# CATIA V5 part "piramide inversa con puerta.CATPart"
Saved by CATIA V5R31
Part number: piramide inversa con puerta
Bounding box of the stored display mesh (mm): x -150 to 150, y 0 to 3.3, z 0 to 175
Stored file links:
  C:\Users\189361\Desktop\piramide inversa con puerta.CATPart
  C:\Users\189361\Desktop\pieamide inversa.CATPart
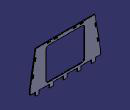
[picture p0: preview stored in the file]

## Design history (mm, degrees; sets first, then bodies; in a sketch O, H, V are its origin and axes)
Body1 (main body)
  Sketch1 on zx-plane, origin (0, 0, 0), H (-1, 0, 0), V (0, 0, 1)
    line L1 (-127.65, 15) -> (-150, 15)
    construction line L2 through (0, 0) direction (0, 1)
    line L3 (-150, 15) -> (-150, 35)
    point P1 (-127.65, 0)
    line L4 (-127.65, 15) -> (-127.65, 0)
    line L5 (-127.65, 0) -> (-112.35, 0)
    point P2 (-112.35, 15)
    line L6 (-112.35, 0) -> (-112.35, 15)
    line L7 (-112.35, 15) -> (-67.65, 15)
    point P3 (-67.65, 0)
    line L8 (-67.65, 15) -> (-67.65, 0)
    line L9 (-67.65, 0) -> (-52.35, 0)
    point P4 (-52.35, 15)
    line L10 (-52.35, 0) -> (-52.35, 15)
    point P5 (0, 20)
    construction line L11 (-120, 69.0879) -> (-120, 15.3646)
    construction line L12 (-60, 77.7749) -> (-60, 37.1309)
    point P6 (0, 20)
    line L13 (-52.35, 15) -> (-7.65, 15)
    point P7 (-7.65, 0)
    line L14 (-7.65, 15) -> (-7.65, 0)
    line L15 (-7.65, 0) -> (0, 0)
    point P8 (0, 20)
    point P9 (0, 20)
    point P10 (0, 0)
    point P11 (-127.65, 15)
    point P12 (-150, 15)
    point P13 (-150, 35)
    point P14 (-112.35, 0)
    point P15 (-67.65, 15)
    point P16 (-52.35, 0)
    point P17 (0, 20)
    point P18 (-120, 15.3646)
    point P19 (-120, 69.0879)
    point P20 (-60, 37.1309)
    point P21 (-60, 77.7749)
    point P22 (0, 20)
    point P23 (-7.65, 15)
    point P24 (0, 20)
    construction line L16 (0, 0) -> (0, 175)
    point P25 (0, 175)
    axis line L17 (0, 175) -> (-53, 175)
    point P26 (-53, 175)
    line L18 (0, 175) -> (-127, 175)
    point P27 (-127, 175)
    line L19 (-127, 175) -> (-150, 35)
    point P28 (0, 0)
    point P29 (127.65, 0)
    point P30 (112.35, 15)
    point P31 (67.65, 0)
    point P32 (52.35, 15)
    point P33 (0, 20)
    point P34 (120, 15.3646)
    point P35 (120, 69.0879)
    construction line L20 (120, 69.0879) -> (120, 15.3646)
    point P36 (60, 37.1309)
    point P37 (60, 77.7749)
    construction line L21 (60, 77.7749) -> (60, 37.1309)
    point P38 (0, 20)
    point P39 (7.65, 0)
    point P40 (0, 20)
    point P41 (0, 20)
    point P42 (0, 0)
    point P43 (127.65, 15)
    point P44 (150, 15)
    point P45 (150, 35)
    point P46 (112.35, 0)
    point P47 (67.65, 15)
    point P48 (52.35, 0)
    point P49 (0, 20)
    point P50 (0, 20)
    point P51 (7.65, 15)
    point P52 (0, 20)
    point P53 (0, 175)
    point P54 (53, 175)
    construction line L22 (0, 175) -> (53, 175)
    point P55 (127, 175)
    line L23 (127.65, 15) -> (150, 15)
    line L24 (150, 15) -> (150, 35)
    line L25 (127.65, 15) -> (127.65, 0)
    line L26 (127.65, 0) -> (112.35, 0)
    line L27 (112.35, 0) -> (112.35, 15)
    line L28 (112.35, 15) -> (67.65, 15)
    line L29 (67.65, 15) -> (67.65, 0)
    line L30 (67.65, 0) -> (52.35, 0)
    line L31 (52.35, 0) -> (52.35, 15)
    line L32 (52.35, 15) -> (7.65, 15)
    line L33 (7.65, 15) -> (7.65, 0)
    line L34 (7.65, 0) -> (0, 0)
    line L35 (0, 175) -> (127, 175)
    line L36 (127, 175) -> (150, 35)
    distance L11 L3 = 30
    distance L6 L11 = 7.65
    distance L12 L11 = 60
    distance L10 L12 = 7.65
    distance L2 L14 = 7.65
    length L14 = 15
    length L13 = 44.7
    length L3 = 20
    length L9 = 15.3
    length L16 = 175
    length L17 = 53
    length L18 = 127
    vertical: L3 L2, L4 L2, L6 L2, L8 L2, L10 L2, L11 L2, L12 L2, L16 V
    coincidence: P2 L1, P4 L1, P5 L2, O L2, L5 H, L13 L7, L15 H, P10 L2, P10 P42, P25 P53
    equal size: L4 L6, L6 L8, L8 L10, L9 L5, L10 L14, L14 L4
    symmetry: P5 P6 L2, P5 P8 L2, P6 P9 L2, P5 P17 L2, P6 P22 L2, P8 P24 L2, O P28 L16, P1 P29 L16, P2 P30 L16, P3 P31 L16, P4 P32 L16, P5 P33 L16, P18 P34 L16, P19 P35 L16, L11 L20 L16, P20 P36 L16, P21 P37 L16, L12 L21 L16, P6 P38 L16, P7 P39 L16, P8 P40 L16, P9 P41 L16, P10 P42 L16, P11 P43 L16, P12 P44 L16, P13 P45 L16, P14 P46 L16, P15 P47 L16, P16 P48 L16, P17 P49 L16, P22 P50 L16, P23 P51 L16, P24 P52 L16, P25 P53 L16, P26 P54 L16, L17 L22 L16, P27 P55 L16, L1 L23 L16, L3 L24 L16, L4 L25 L16, L5 L26 L16, L6 L27 L16, L7 L28 L16, L8 L29 L16, L9 L30 L16, L10 L31 L16, L13 L32 L16, L14 L33 L16, L15 L34 L16, L18 L35 L16, L19 L36 L16
    perpendicularity: L6 L7
    horizontal: L17 H, L18 H
  Pad1: profile Sketch1, direction (0, 1, 0), length 3.3
  Sketch2 on end face of Pad1, origin (0, 3.3, 0), H (-1, 0, 0), V (0, 0, 1)
    line L1 (-47.5, 172) -> (-32.5, 172)
    line L2 (-32.5, 168.7) -> (-47.5, 168.7)
    line L3 (-32.5, 172) -> (-32.5, 168.7)
    line L4 (-47.5, 168.7) -> (-47.5, 172)
    construction line L5 (-40, 200.409) -> (-40, 181.2846)
    line L6 (-141.3626, 69.0701) -> (-138.1062, 68.5351)
    line L7 (-138.1062, 68.5351) -> (-135.6745, 83.3367)
    line L8 (-135.6745, 83.3367) -> (-138.9309, 83.8717)
    line L9 (-138.9309, 83.8717) -> (-141.3626, 69.0701)
    construction line L10 (-146.6312, 37) -> (-125.5566, 165.2804)
    construction line L11 (-143.6709, 36.5137) -> (-146.6312, 37)
    construction line L12 (-122.5963, 164.7941) -> (-143.6709, 36.5137)
    construction line L13 (-125.5566, 165.2804) -> (-122.5963, 164.7941)
    point P1 (-146.6312, 37)
    construction line L14 (-117.5, 169) -> (-117.5, 172)
    construction line L15 (-162.6915, 80.1747) -> (-181.1718, 83.2107)
    construction line L16 (-159.9601, 110.1281) -> (-179.3888, 113.32)
    point P2 (-129.2041, 143.078)
    point P3 (-141.3626, 69.0701)
    point P4 (-131.6358, 128.2764)
    point P5 (-138.9309, 83.8717)
    line L17 (-131.6358, 128.2764) -> (-129.2041, 143.078)
    point P6 (-125.9478, 142.543)
    point P7 (-138.1062, 68.5351)
    line L18 (-129.2041, 143.078) -> (-125.9478, 142.543)
    point P8 (-128.3795, 127.7415)
    point P9 (-135.6745, 83.3367)
    line L19 (-125.9478, 142.543) -> (-128.3795, 127.7415)
    line L20 (-128.3795, 127.7415) -> (-131.6358, 128.2764)
    axis line L21 (-55, 181.2846) -> (-55, 200.409)
    point P10 (-77.5, 172)
    point P11 (-32.5, 172)
    point P12 (-62.5, 172)
    point P13 (-47.5, 172)
    line L22 (-62.5, 172) -> (-77.5, 172)
    point P14 (-62.5, 168.7)
    point P15 (-47.5, 168.7)
    line L23 (-62.5, 168.7) -> (-62.5, 172)
    point P16 (-77.5, 168.7)
    point P17 (-32.5, 168.7)
    line L24 (-77.5, 168.7) -> (-62.5, 168.7)
    line L25 (-77.5, 172) -> (-77.5, 168.7)
    point P18 (-40, 181.2846)
    point P19 (-40, 200.409)
    point P21 (-122.5963, 164.7941)
    point P22 (-125.5566, 165.2804)
    point P23 (-117.5, 172)
    point P24 (-117.5, 169)
    point P25 (-181.1718, 83.2107)
    point P26 (-162.6915, 80.1747)
    point P27 (-179.3888, 113.32)
    point P28 (-159.9601, 110.1281)
    point P29 (-55, 200.409)
    point P30 (-55, 181.2846)
    reference projected point E1 (-150, 35) from vertex [face of Pad1 from Sketch1.L3 | end face of Pad1 | face of Pad1 from Sketch1.L19]
    reference projected line E2 (0, 175) -> (-127, 175) from edge [face of Pad1 from Sketch1.L18 | end face of Pad1]
    reference projected line E3 (-127, 175) -> (-150, 35) from edge [face of Pad1 from Sketch1.L19 | end face of Pad1]
    point P31 (40, 181.2846)
    point P32 (40, 200.409)
    construction line L26 (40, 200.409) -> (40, 181.2846)
    point P33 (122.5963, 164.7941)
    point P34 (125.5566, 165.2804)
    construction line L27 (125.5566, 165.2804) -> (122.5963, 164.7941)
    point P35 (117.5, 172)
    point P36 (117.5, 169)
    construction line L28 (117.5, 169) -> (117.5, 172)
    point P37 (181.1718, 83.2107)
    point P38 (162.6915, 80.1747)
    construction line L29 (162.6915, 80.1747) -> (181.1718, 83.2107)
    point P39 (179.3888, 113.32)
    point P40 (159.9601, 110.1281)
    construction line L30 (159.9601, 110.1281) -> (179.3888, 113.32)
    point P41 (129.2041, 143.078)
    point P42 (141.3626, 69.0701)
    point P43 (131.6358, 128.2764)
    point P44 (138.9309, 83.8717)
    point P45 (125.9478, 142.543)
    point P46 (138.1062, 68.5351)
    point P47 (128.3795, 127.7415)
    point P48 (135.6745, 83.3367)
    point P49 (77.5, 172)
    point P50 (32.5, 172)
    point P51 (62.5, 172)
    point P52 (47.5, 172)
    point P53 (62.5, 168.7)
    point P54 (47.5, 168.7)
    point P55 (77.5, 168.7)
    point P56 (32.5, 168.7)
    point P57 (55, 200.409)
    point P58 (55, 181.2846)
    construction line L31 (55, 181.2846) -> (55, 200.409)
    line L32 (47.5, 172) -> (32.5, 172)
    line L33 (32.5, 168.7) -> (47.5, 168.7)
    line L34 (32.5, 172) -> (32.5, 168.7)
    line L35 (47.5, 168.7) -> (47.5, 172)
    line L36 (141.3626, 69.0701) -> (138.1062, 68.5351)
    line L37 (138.1062, 68.5351) -> (135.6745, 83.3367)
    line L38 (135.6745, 83.3367) -> (138.9309, 83.8717)
    line L39 (138.9309, 83.8717) -> (141.3626, 69.0701)
    line L40 (131.6358, 128.2764) -> (129.2041, 143.078)
    line L41 (129.2041, 143.078) -> (125.9478, 142.543)
    line L42 (125.9478, 142.543) -> (128.3795, 127.7415)
    line L43 (128.3795, 127.7415) -> (131.6358, 128.2764)
    line L44 (62.5, 172) -> (77.5, 172)
    line L45 (62.5, 168.7) -> (62.5, 172)
    line L46 (77.5, 168.7) -> (62.5, 168.7)
    line L47 (77.5, 172) -> (77.5, 168.7)
    construction line L48 (-117.65, 100) -> (-87.65, 100)
    construction line L49 (-87.65, 100) -> (-87.65, 160)
    construction line L50 (-87.65, 160) -> (-117.65, 160)
    construction line L51 (-117.65, 160) -> (-117.65, 100)
    construction line L52 (-117.65, 25) -> (-87.65, 25)
    construction line L53 (-87.65, 85) -> (-117.65, 85)
    construction line L54 (-87.65, 25) -> (-87.65, 85)
    construction line L55 (-117.65, 85) -> (-117.65, 25)
    reference projected line E4 (-112.35, 15) -> (-67.65, 15) from edge [face of Pad1 from Sketch1.L7 | end face of Pad1]
    reference projected line E5 (-127.65, 15) -> (-127.65, 0) from edge [face of Pad1 from Sketch1.L4 | end face of Pad1]
    point P67 (0, 161)
    line L56 (0, 161) -> (-72.65, 161)
    line L57 (-82.65, 151) -> (-82.65, 34)
    line L58 (-72.65, 24) -> (0, 24)
    point P68 (0, 24)
    point P69 (0, 24)
    point P70 (0, 161)
    arc A1 centre (-72.65, 151) radius 10 from (-82.65, 151) to (-72.65, 161) cw
    point P71 (-82.65, 151)
    point P72 (-72.65, 161)
    arc A2 centre (-72.65, 34) radius 10 from (-72.65, 24) to (-82.65, 34) cw
    point P74 (-72.65, 24)
    point P75 (-82.65, 34)
    point P77 (0, 24)
    point P78 (72.65, 24)
    line L59 (72.65, 24) -> (0, 24)
    point P79 (82.65, 34)
    arc A3 centre (72.65, 34) radius 10 from (72.65, 24) to (82.65, 34) ccw
    point P81 (82.65, 151)
    line L60 (82.65, 151) -> (82.65, 34)
    point P82 (72.65, 161)
    arc A4 centre (72.65, 151) radius 10 from (82.65, 151) to (72.65, 161) ccw
    point P84 (0, 161)
    line L61 (0, 161) -> (72.65, 161)
    length L1 = 15
    length L4 = 3.3
    distance L3 L5 = 7.5
    length L9 = 15
    length L8 = 3.3
    length L11 = 3
    length L10 = 130
    length L14 = 3
    distance L6 L15 = 7.5
    distance L15 L11 = 40
    distance L15 L16 = 30
    distance L21 L5 = 15
    distance L25 L14 = 40
    distance L5 V = 40
    distance P1 E1 V = 2
    distance L22 E2 = 3
    distance L9 E3 = 3
    length L51 = 60
    length L50 = 30
    length L55 = 60
    length L53 = 30
    distance L53 L48 = 15
    distance E4 L52 = 10
    distance L55 E5 = 10
    distance L58 L52 = 1
    distance L57 L54 = 5
    distance L56 L50 = 1
    radius A1 = 10
    radius A2 = 10
    distance L61 L59 = 137 (reference)
    distance L60 L57 = 165.3 (reference)
    distance L14 V = 117.5 (reference)
    horizontal: L1 H, L2 H, L48 H, L50 H, L52 H, L53 H, L56 H, L58 H
    vertical: L3 V, L4 V, L5 V, L14 V, L21 V, L49 V, L51 V, L54 V, L55 V, L57 V
    perpendicularity: L7 L6, L9 L6, L11 L10, L11 L12, L12 L13, L10 L13
    parallelism: L8 L6
    coincidence: L10 L9, L51 L55, P67 V, P68 V, P67 P70, P68 P69
    symmetry: P3 P2 L16, P5 P4 L16, L9 L17 L16, P7 P6 L16, L6 L18 L16, P9 P8 L16, L7 L19 L16, L8 L20 L16, P11 P10 L21, P13 P12 L21, L1 L22 L21, P15 P14 L21, L4 L23 L21, P17 P16 L21, L2 L24 L21, L3 L25 L21, P18 P31 V, P19 P32 V, L5 L26 V, P21 P33 V, P22 P34 V, L13 L27 V, P23 P35 V, P24 P36 V, L14 L28 V, P25 P37 V, P26 P38 V, L15 L29 V, P27 P39 V, P28 P40 V, L16 L30 V, P2 P41 V, P3 P42 V, P4 P43 V, P5 P44 V, P6 P45 V, P7 P46 V, P8 P47 V, P9 P48 V, P10 P49 V, P11 P50 V, P12 P51 V, P13 P52 V, P14 P53 V, P15 P54 V, P16 P55 V, P17 P56 V, P29 P57 V, P30 P58 V, L21 L31 V, L1 L32 V, L2 L33 V, L3 L34 V, L4 L35 V, L6 L36 V, L7 L37 V, L8 L38 V, L9 L39 V, L17 L40 V, L18 L41 V, L19 L42 V, L20 L43 V, L22 L44 V, L23 L45 V, L24 L46 V, L25 L47 V, P68 P69 V, P67 P70 V, P68 P77 V, P74 P78 V, L58 L59 V, P75 P79 V, A2 A3 V, P71 P81 V, L57 L60 V, P72 P82 V, A1 A4 V, P67 P84 V, L56 L61 V
    tangency: A1 L57, A1 L56, A2 L58, A2 L57
  Pocket1: profile Sketch2, direction (0, -1, 0), length 3.3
